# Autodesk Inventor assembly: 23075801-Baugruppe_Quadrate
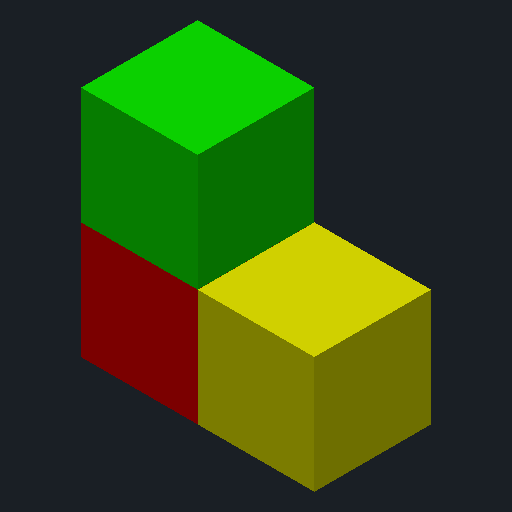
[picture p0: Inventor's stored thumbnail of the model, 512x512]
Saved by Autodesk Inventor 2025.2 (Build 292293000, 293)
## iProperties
Company: Ed. Züblin AG
Created: 2025-03
Part Number: 23075801-Baugruppe_Quadrate
Material: Stahlbeton C30/37
Document SubType Name: Assembly
Designer: FrodlSte
Mass: 7.5e+06 g
Surface Area: 180000 cm^2
Volume: 3e+06 cm^3
Density: 2.5 g/cm^3
Description: Ausbruch
z_Bereich: Tunnelbau
z_Direktion: Tief- und Tunnelbau
z_Konzerneinheit: Zentrale Technik
cpiComponentType: Attribut
cpiFitMatchkey: =<z_Matchkey>
z_Matchkey: =<z_Matchkey_010>_<z_Matchkey_020>_<z_Matchkey_030>_<z_Matchkey_040>_<z_Matchkey_050>_<z_Matchkey_060>_<z_Matchkey_070>_<z_Matchkey_080>_<z_Matchkey_090>_<z_Mat
z_Matchkey_010: xxxxx
z_Matchkey_020: 5DTUB
z_Matchkey_030: xxx
z_Matchkey_040: xxx
z_Matchkey_050: xxx
z_Matchkey_060: xxx
z_Matchkey_070: xxx
z_Matchkey_080: xxx
z_Matchkey_090: xxx
z_Matchkey_100: xxx
z_Matchkey_110: xxx
z_Matchkey_120: xxxxxxx
z_Matchkey_130: KALO
z_Matchkey_140: xxxx
DocNumber: 23075801-Baugruppe_Quadrate.iam
Folder: DL23075801-DE-Pfaffensteigtunnel\BIM\Testmodell
VDS_Category: 09 - BIM - Konstruktion
Author: FrodlSte
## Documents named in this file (4)
- C:\z_Vault\CAD\DL23075801-DE-Pfaffensteigtunnel\BIM\Testmodell\23075801-Baugruppe_Quadrate.iam
- C:\z_Vault\CAD\DL23075801-DE-Pfaffensteigtunnel\BIM\Testmodell\23075801-Quadrat_1.ipt
- C:\z_Vault\CAD\DL23075801-DE-Pfaffensteigtunnel\BIM\Testmodell\23075801-Quadrat_2.ipt
- C:\z_Vault\CAD\DL23075801-DE-Pfaffensteigtunnel\BIM\Testmodell\23075801-Quadrat_3.ipt
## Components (3 placed, 3 different names)
1. 23075801-Quadrat_1:1
2. 23075801-Quadrat_2:1
3. 23075801-Quadrat_3:1
